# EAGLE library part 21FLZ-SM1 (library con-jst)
CONNECTOR
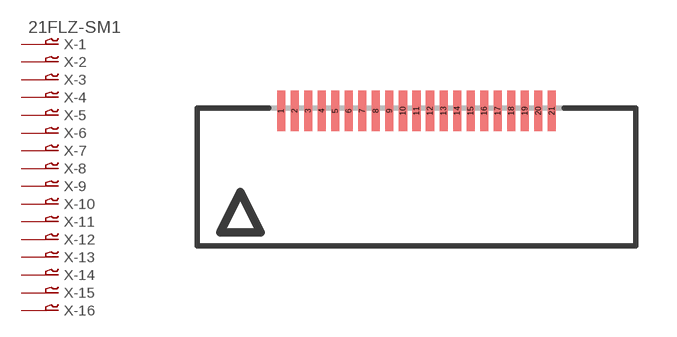
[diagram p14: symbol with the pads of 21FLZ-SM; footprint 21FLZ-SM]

Designator prefix X; gates -1=P-VN -2=P-N -3=P-N -4=P-N -5=P-N -6=P-N -7=P-N -8=P-N -9=P-N -10=P-N -11=P-N -12=P-N -13=P-N -14=P-N -15=P-N -16=P-N -17=P-N -18=P-N -19=P-N -20=P-N -21=P-N

## 21FLZ-SM1 (OC_FARNELL: unknown; OC_NEWARK: unknown)  [21FLZ-SM]
1  -1:1  pas
2  -2:1  pas
3  -3:1  pas
4  -4:1  pas
5  -5:1  pas
6  -6:1  pas
7  -7:1  pas
8  -8:1  pas
9  -9:1  pas
10  -10:1  pas
11  -11:1  pas
12  -12:1  pas
13  -13:1  pas
14  -14:1  pas
15  -15:1  pas
16  -16:1  pas
17  -17:1  pas
18  -18:1  pas
19  -19:1  pas
20  -20:1  pas
21  -21:1  pas

## Footprint 21FLZ-SM (pad centres in mm)
CONNECTOR
smd 0.3 x 1.5: 1 -5,2.5; 2 -4.5,2.5; 3 -4,2.5; 4 -3.5,2.5; 5 -3,2.5; 6 -2.5,2.5; 7 -2,2.5; 8 -1.5,2.5; 9 -1,2.5; 10 -0.5,2.5; 11 0,2.5; 12 0.5,2.5; 13 1,2.5; 14 1.5,2.5; 15 2,2.5; 16 2.5,2.5; 17 3,2.5; 18 3.5,2.5; 19 4,2.5; 20 4.5,2.5; 21 5,2.5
